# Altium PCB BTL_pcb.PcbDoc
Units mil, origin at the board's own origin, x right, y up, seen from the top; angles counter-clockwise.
Board outline 6000 x 4000 mil, 2 copper layers (Top Layer, Bottom Layer); 11 components, 6 nets, 26 pads, 0 vias.
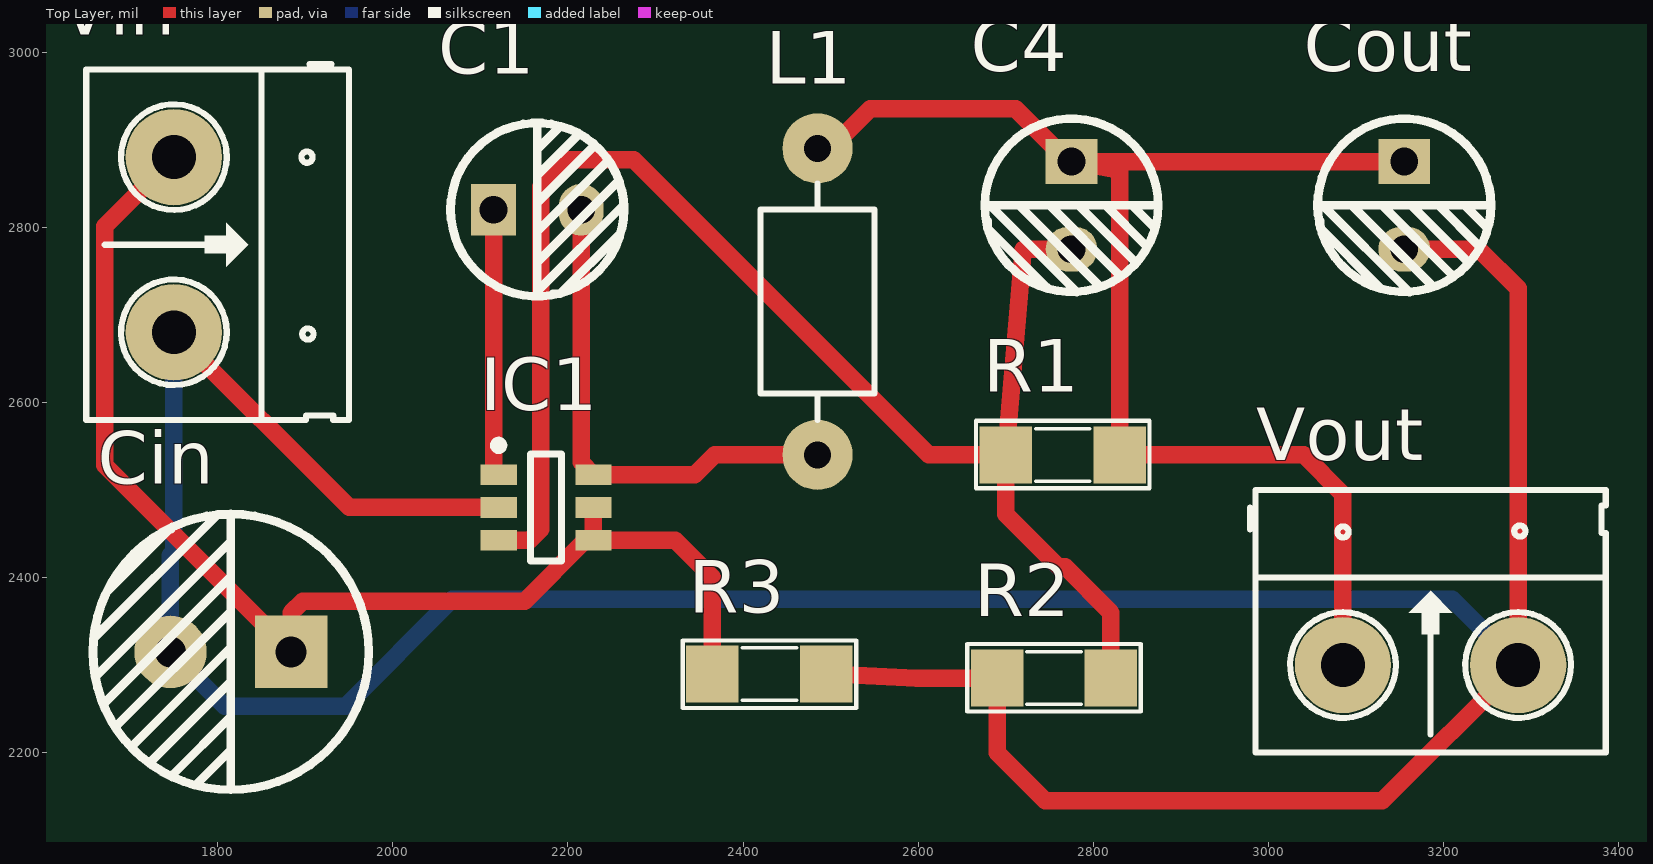
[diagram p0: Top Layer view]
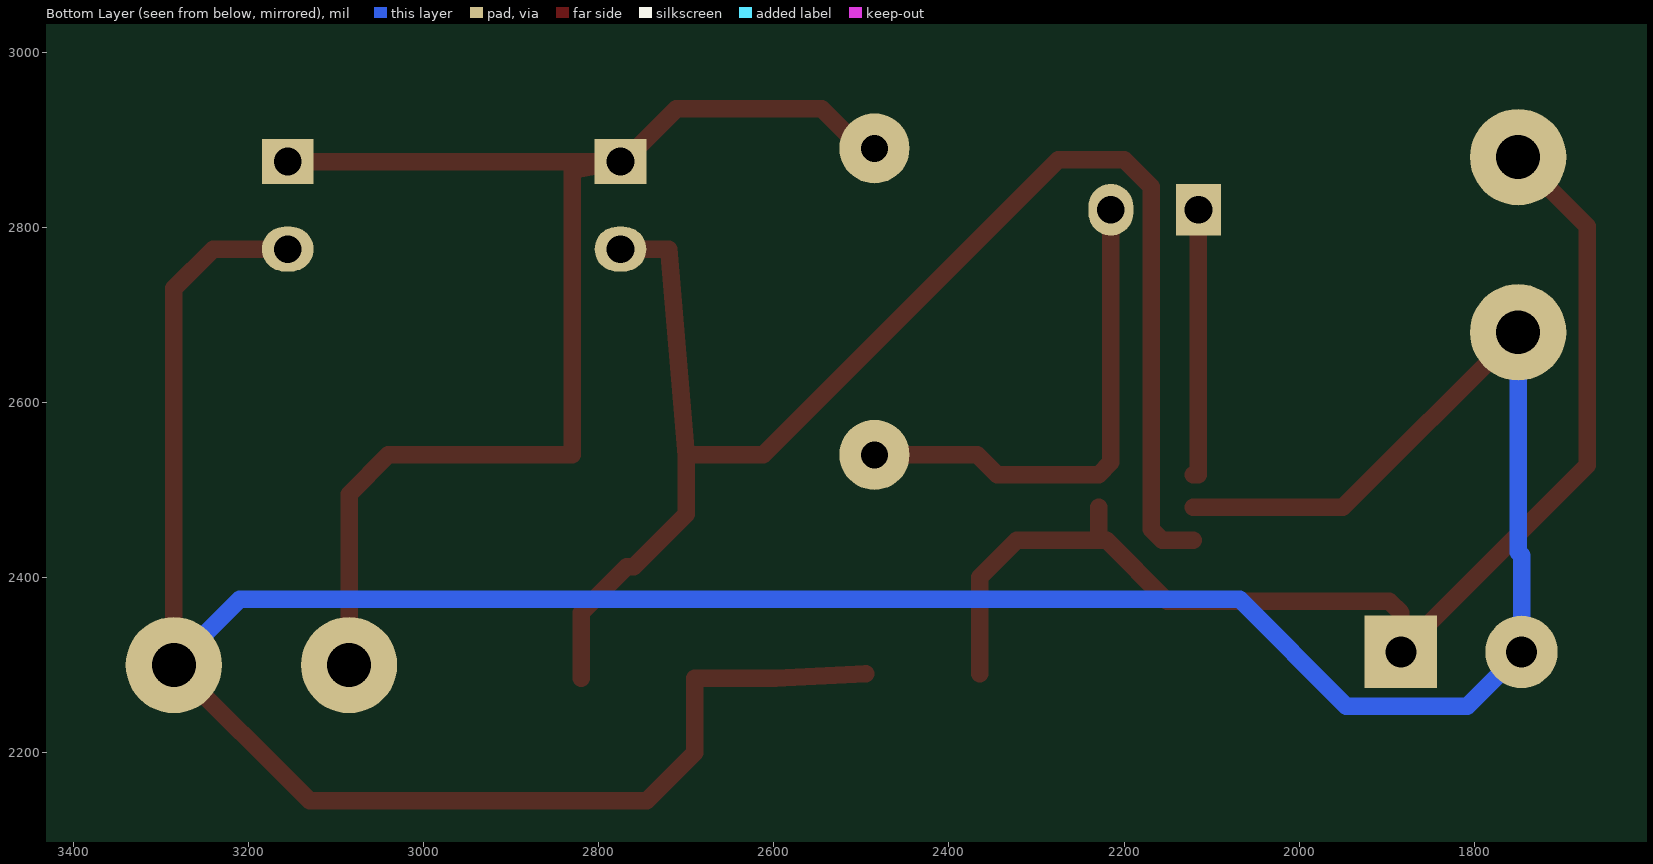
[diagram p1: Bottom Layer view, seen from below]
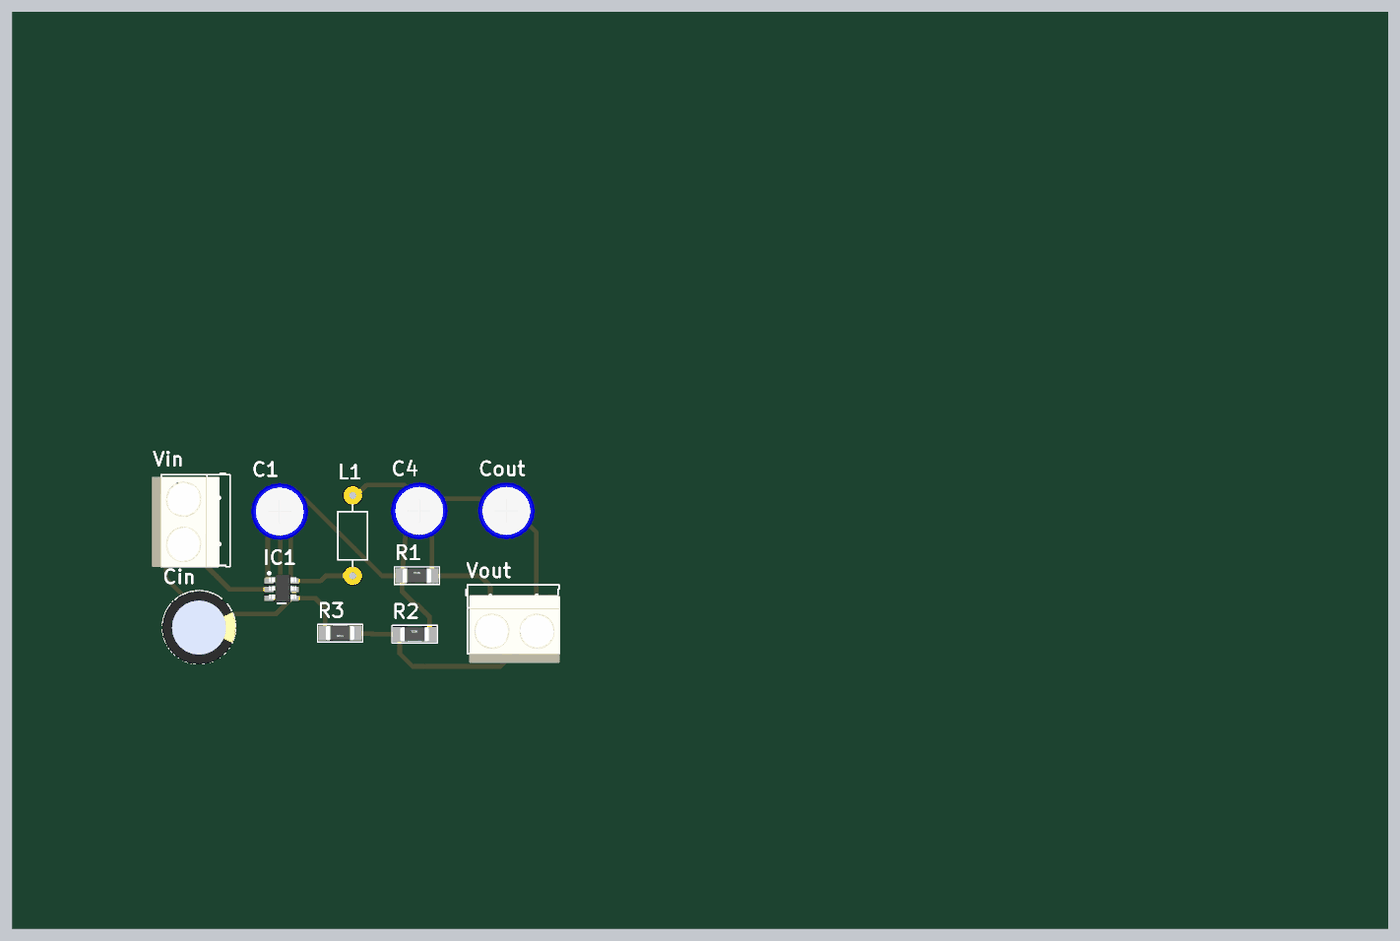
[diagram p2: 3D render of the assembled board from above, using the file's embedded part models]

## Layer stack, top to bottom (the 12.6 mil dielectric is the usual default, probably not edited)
Top Solder: solder mask 0.4, Solder Resist, Dk 3.5
Top Layer: signal copper 1.4
Dielectric 1: dielectric 12.6, FR-4, Dk 4.8
Bottom Layer: signal copper 1.4
Bottom Solder: solder mask 0.4, Solder Resist, Dk 3.5

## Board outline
1000,1000 7000,1000 7000,5000 1000,5000

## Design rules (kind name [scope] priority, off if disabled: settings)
Clearance [All] p1: gap=10 ignorepadtopadclearanceinfootprint=FALSE except(0: Arc-Hole Track-Hole SMDPad-Hole THPad-Hole Via-Hole Fill-Hole Poly-Hole Region-Hole Text-Hole)
PolygonConnect [All] p1: connectstyle=Relief reliefconductorwidth=10 reliefentries=4 polygonreliefangle="90 Angle" airgapwidth=10
RoomDefinition BTL [InComponentClass('BTL')] p1: confinementstyle=ConfineIn formatcopy=TRUE lockcomponents=FALSE outline 7045,1060 10110,1060 10110,1610 7045,1610
RoutingVias [All] p1: holewidth=28 width=50 viastyle="Through Hole" minholewidth=20 minwidth=50 maxholewidth=28 maxwidth=50
SolderMaskExpansion [All] p1: expansion=4 istentingtop=FALSE
Width [All] p1: maxlimit=30 minlimit=10 preferedwidth=20 minimp=50.000000 maximp=50.000000 favimp=50.000000
30 further rules are at their usual default settings.

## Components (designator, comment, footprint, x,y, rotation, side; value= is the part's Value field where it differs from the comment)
C1 "0.1uF" "tu hoa 5mm" 2165,2820 r0 top
C4 "22pF" "tu hoa 5mm" 2775,2825 r270 top
Cin "10uF" "tu hoa 8mm" 1815,2315 r180 top
Cout "22uF" "tu hoa 5mm" 3155,2825 r270 top
IC1 "SY8120B1ABC" SY8120B1ABC_SOT23 2175,2480 r0 top
L1 "4.7uH" L/0.4 2485,2540 r90 top value="150 mH"
R1 "100k" SM-RES-1206 2700,2540 r0 top value="R1/4W - 1K"
R2 "22.1k" SM-RES-1206 2690,2285 r0 top value="R1/4W - 1K"
R3 "1M" SM-RES-1206 2495,2290 r180 top value="R1/4W - 1K"
Vin "Header 2" HED2 1750,2880 r270 top
Vout "Header 2" HED2 3085,2300 r0 top

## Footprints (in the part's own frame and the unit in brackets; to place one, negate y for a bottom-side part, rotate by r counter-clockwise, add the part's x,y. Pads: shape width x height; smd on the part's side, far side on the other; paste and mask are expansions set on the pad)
HED2 [mil] "Header 2, 2 pin, hight 300mil, Pin to Pin 200, Colour Green"
  round 110 hole 50: 1(0,0) 2(200,0)
  silkscreen extent -106,-100 300,200, body extent -92,-140 302,155, height 394
L/0.4 [mil] "Inductor , 2 Pin, L 350mil, W 150 mil"
  round 80 hole 31: 1(0,0) 2(350,0)
  silkscreen extent 40,-65 310,65
SM-RES-1206 [mil]
  rect 60x65 smd: 1(0,0) 2(130,0)
  silkscreen extent -34,-38 164,39, body extent 2,-31 128,32, height 40
SY8120B1ABC_SOT23 [mm]
  rect 1.05x0.6 smd: 1(-1.375,0.95) 2(-1.375,0) 3(-1.375,-0.95) 4(1.375,-0.95) 5(1.375,0) 6(1.375,0.95)
  silkscreen extent -1.5,-1.55 0.45,1.92, body extent -1.37,-1.42 1.63,1.68, height 1.4
"tu hoa 5mm" [mm]
  rect 1.3x1.5 hole 0.8: 1(-1.27,0)
  oval 1.3x1.5 hole 0.8: 2(1.27,0)
  silkscreen extent -2.51,-2.51 2.51,2.51, body extent -3.12,-3.18 3.23,3.18, height 14.55
"tu hoa 8mm" [mm]
  rect 2.1x2.1 hole 0.9: 1(-1.75,0)
  round 2.1 hole 0.9: 2(1.75,0)
  silkscreen extent -4,-4 4,4, body extent -4.1,-4.07 4.1,4.13, height 13.81

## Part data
C1: library part "Tu Hoa 0.1uF 50V 5x11", "Cắm"
C4: library part "Tu Hoa 2.2uF 100V 5x11", "Cắm"
Cin: library part "Tu Hoa 4.7uF 400V 8x12", "Cắm"
Cout: library part "Tu Hoa 22uF 25V 5x11", "Cắm"
IC1: Package=None
L1: library part L1, "Inductor"
R1 R2 R3: library part R, "Resistor 1/4W"
Vin Vout: library part Hed2, "Header 2 (Green)"

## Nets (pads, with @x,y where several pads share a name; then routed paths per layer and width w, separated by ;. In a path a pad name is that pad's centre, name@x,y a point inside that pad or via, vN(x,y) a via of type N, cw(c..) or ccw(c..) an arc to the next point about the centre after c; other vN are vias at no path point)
GND: Cin.2 Cout.2 IC1.2 R2.1 R3.1 Vin.2 Vout.2 | length 4007.2
  Top Layer w20: Vin.2 1950,2480 IC1.2 ; R3.1 2598,2285 R2.1 2690,2200 2745,2145 3130,2145 Vout.2 3285,2730 3240,2775 Cout.2
  Bottom Layer w20: Vin.2 1750,2429 1746.1,2425.1 Cin.2 1808.1,2253 1946,2253 2068,2375 3210,2375 Vout.2
NetC1_1: C1.1 IC1.1 | length 308.5
  Top Layer w20: C1.1 2115,2517.4 IC1.1
NetC1_2: C1.2 IC1.6 L1.1 | length 573.7
  Top Layer w20: C1.2 2215,2531.54 IC1.6 2345,2517.4 2367.6,2540 L1.1
NetC4_1: C4.1 Cout.1 L1.2 R1.2 Vout.1 | length 1563
  Top Layer w20: L1.2 2500,2890 2545,2935 2711.06,2935 2771.06,2875 C4.1 ; Vout.1 3085,2495 3040,2540 R1.2 2830,2865 C4.1 ; Cout.1 C4.1
NetC4_2: C4.2 IC1.3 R1.1 R2.2 | length 1727.9
  Top Layer w20: IC1.3 2156.6,2442.6 2169,2455 2169,2846 2200,2877 2275,2877 2612,2540 R1.1 ; C4.2 2720,2775 R1.1 ; R2.2 2820,2360 2768,2412 2760,2412 2700,2472 R1.1
NetCin_1: Cin.1 IC1.4 IC1.5 R3.2 Vin.1 | length 1411.3
  Top Layer w20: Vin.1 1671,2801 1671,2527.9 Cin.1 1883.9,2360 1896.9,2373 2150.4,2373 2220,2442.6 IC1.4 ; IC1.5 IC1.4 ; R3.2 2365,2400 2322.4,2442.6 IC1.4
